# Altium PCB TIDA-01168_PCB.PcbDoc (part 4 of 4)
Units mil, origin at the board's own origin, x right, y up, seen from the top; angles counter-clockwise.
Board outline 7874.02 x 8344.02 mil, 4 copper layers (Top Layer, Signal Layer 1, Signal Layer 2, Bottom Layer), stack 65.748 mil thick; 480 components, 223 nets, 1266 pads, 1791 vias.
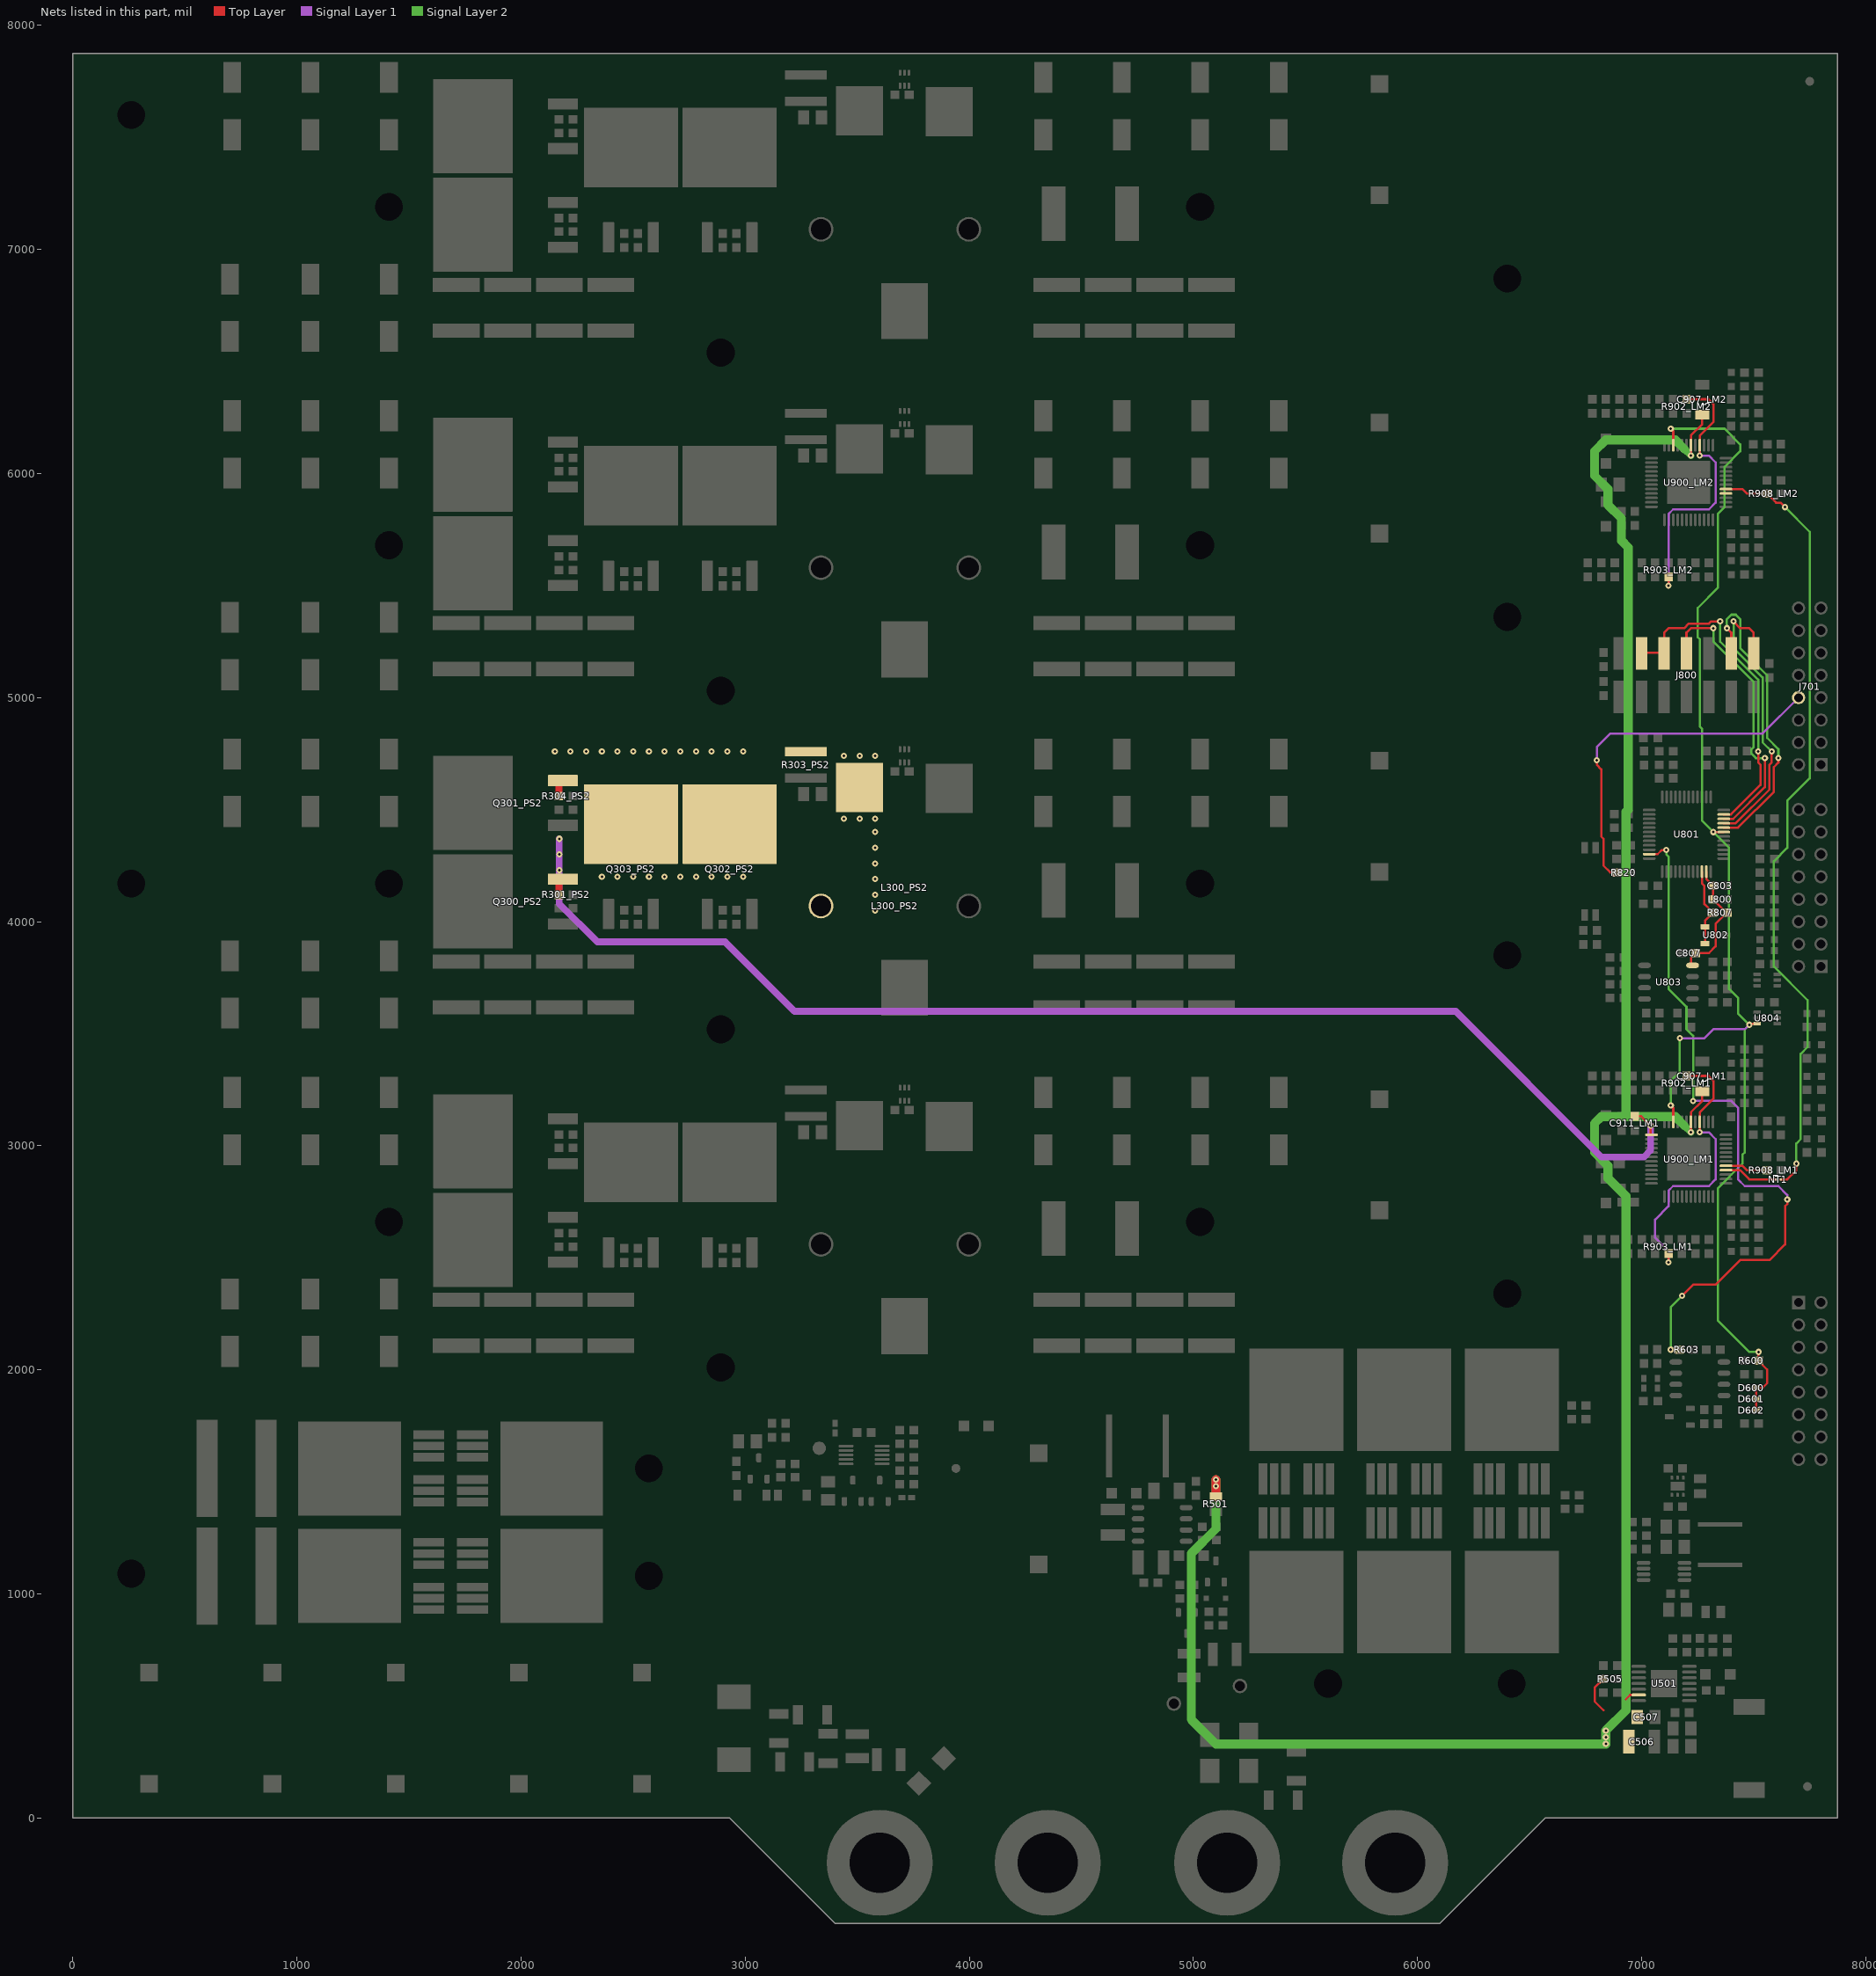
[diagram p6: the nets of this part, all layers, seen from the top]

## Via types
v1: diameter 28, hole 12, Top Layer to Bottom Layer, 1729 vias
v2: diameter 19.68, hole 7.87, Top Layer to Bottom Layer, 52 vias
v3: diameter 15.75, hole 7.87, Top Layer to Bottom Layer, 9 vias
v4: diameter 29, hole 12, Top Layer to Bottom Layer, 1 vias

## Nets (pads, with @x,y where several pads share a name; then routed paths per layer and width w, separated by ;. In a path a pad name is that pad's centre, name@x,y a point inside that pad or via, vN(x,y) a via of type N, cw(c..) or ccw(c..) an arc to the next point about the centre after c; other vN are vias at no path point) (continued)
SW2_B: C911_LM1.1 L300_PS2.2 Q300_PS2.3 Q301_PS2.3 Q302_PS2.4 Q303_PS2.4 R301_PS2.2 R303_PS2.2 R304_PS2.2 U900_LM1.13 | length 6010.6
  Top Layer w10: C911_LM1.1@6970,3131.5 6998.5,3131.5 v1(7040,3090) 7040,3051.93 U900_LM1.13@7043.66,3048.27
  Top Layer w30: R301_PS2.2@2168.5,4120 Q300_PS2.3@2168.5,4172.44 ; R304_PS2.2@2168.5,4560 2168.5,4612.44 Q301_PS2.3@2186.06,4630
  Signal Layer 1 w30: v1(2170,4370) v1(2170,4300) v1(2170,4230) 2170,4080 2340,3910 2910,3910 3220,3600 6170,3600 6820,2950 7010,2950 7040,2980 v1(7040,3090)
  other v1: 3580,4050 3580,4120 3580,4190 2360,4200 2430,4200 2500,4200 2570,4200 2640,4200 2710,4200 2780,4200 2850,4200 2920,4200 2990,4200 3580,4260 3580,4330 3580,4400 3440,4460 3510,4460 3580,4460 3440,4740 3510,4740 3580,4740 2150,4760 2220,4760 2290,4760 2360,4760 2430,4760 2500,4760 2570,4760 2640,4760 2710,4760 2780,4760 2850,4760 2920,4760 2990,4760
SYNCIN_A: U900_LM2.40
SYNCIN_B: NT1.2 U900_LM1.40 | length 240.6
  Top Layer w10: U900_LM1.40@7376.34,2890.79 7439.21,2890.79 7480,2850 NT1.2@7600,2850
SYNCOUT_A: NT1.1 R908_LM2.2 U900_LM2.41 | length 3538.2
  Top Layer w10: U900_LM2.41@7376.34,5930.47 7449.53,5930.47 7470,5910 R908_LM2.2@7558.5,5910 7560,5910 7600,5870 7620,5870 v1(7640,5850) ; NT1.1@7620,2850 7650,2850 7690,2890 v1(7690,2920)
  Signal Layer 2 w10: v1(7640,5850) 7750,5740 7750,4640 7650,4540 7650,4330 7590,4270 7590,3800 7740,3650 7740,3440 7710,3410 7710,3030 7690,3010 v1(7690,2920)
SYNCOUT_B: R908_LM1.2 U900_LM1.41 | length 190.6
  Top Layer w10: U900_LM1.41@7376.34,2910.47 7449.53,2910.47 7470,2890 R908_LM1.2@7558.5,2890
TCK: J800.9 J800.11 U801.23 | length 1484.3
  Top Layer w10: J800.11@7000,5202.31 7002.31,5200 7100,5200 7100,5290 7120,5310 7190,5310 7210,5330 7300,5330 7310,5340 v1(7350,5340) ; U801.23@7366.34,4478.58 7398.58,4478.58 7530,4610 7530,4700 7520,4710 v1(7520,4760)
  Signal Layer 2 w10: v1(7350,5340) 7350,5250 7520,5080 v1(7520,4760)
TDI: J800.3 U801.20 | length 1371.4
  Top Layer w10: U801.20@7366.34,4419.53 7429.53,4419.53 7590,4580 7590,4690 7610,4710 v1(7610,4730) ; v1(7380,5310) 7400,5290 J800.3@7400,5202.31
  Signal Layer 2 w10: v1(7380,5310) 7380,5350 7400,5370 7420,5370 7440,5350 7440,5220 7560,5100 7560,4820 7610,4770 v1(7610,4730)
TDO: J800.7 U801.22 | length 1295.1
  Top Layer w10: J800.7@7200,5202.31 7200,5290 7220,5310 v1(7320,5310) ; U801.22@7366.34,4458.9 7408.9,4458.9 7550,4600 v1(7550,4730)
  Signal Layer 2 w10: v1(7320,5310) 7320,5250 7500,5070 7500,4780 7490,4770 7490,4750 7510,4730 v1(7550,4730)
TMS: J800.1 U801.21 | length 1289.1
  Top Layer w10: U801.21@7366.34,4439.21 7419.21,4439.21 7570,4590 7570,4700 7580,4710 v1(7580,4760) ; v1(7410,5340) 7440,5310 7480,5310 7500,5290 J800.1@7500,5202.31
  Signal Layer 2 w10: v1(7410,5340) 7410,5220 7540,5090 7540,4800 v1(7580,4760)
TXD: J701.8 R820.1 | length 1604.5
  Top Layer w10: v1(6800,4720) 6800,4700 6820,4680 6820,4380 6830,4370 6830,4250 6860,4220 R820.1@6888.5,4220
  Signal Layer 1 w10: v1(6800,4720) 6800,4780 6860,4840 7540,4840 J701.8@7700,5000
UVLO: D600.2 D601.2 D602.2 R600.1 U801.19 U804.3 U900_LM1.10 U900_LM2.10 | length 5923.3
  Top Layer w10: v1(7130,3180) 7141.1,3168.9 U900_LM1.10@7141.1,3106.34 ; v1(7130,6200) 7141.1,6188.9 U900_LM2.10@7141.1,6126.34 ; v1@7320,4400 v1(7320,4399.84) U801.19@7366.34,4399.84 ; v1(7480,3540) 7484.41,3544.41 U804.3@7515.71,3544.41 ; D602.2@7511.65,1820 D601.2@7511.65,1870 D600.2@7511.65,1920 7540,1920 7560,1940 7560,2001.5 R600.1@7521.5,2040 v1(7521.5,2080)
  Signal Layer 1 w10: v1(7170,3480) 7280,3480 7320,3520 7460,3520 v1(7480,3540)
  Signal Layer 2 w10: v1(7130,3180) 7130,3290 7170,3330 v1(7170,3480) ; v1(7130,6200) 7370,6200 7440,6130 7440,6100 7370,6030 7370,5850 7340,5820 7340,5490 7250,5400 7250,5270 7260,5260 7260,4870 7270,4860 7270,4450 v1@7320,4400 ; v1(7320,4399.84) 7390,4329.84 7390,3700 7430,3660 7430,3590 v1(7480,3540) 7460,3520 7460,2970 7450,2960 7450,2920 7340,2810 7340,2220 7480,2080 v1@7520,2080
VDDA: C803.2 C807.1 L800.2 R807.1 U801.11 U803.8 | length 545.6
  Top Layer w10: U803.8@7226.54,3804.25 7220,3810.79 7220,3838.5 C807.1@7231.81,3850.31 ; C807.1@7241.5,3860 7300,3860 7330,3890 7330,3990 7378.5,4038.5 7378.5,4040 L800.2@7318.5,4100 C803.2@7318.5,4160 7288.58,4189.92 U801.11@7288.58,4223.66
VIN_LM: C506.1 C507.1 C907_LM1.1 C907_LM2.1 R501.2 R505.1 U501.13 U900_LM1.6 U900_LM2.6 | length 10583.7
  Top Layer w10: R505.1@6828.5,620 6790,581.5 6790,520 6830,480 ; 6930,530 6948.82,548.82 U501.13@6986.81,548.82 ; U900_LM1.6@7219.69,3106.18 7219.69,3149.69 7269.84,3199.84 C907_LM1.1@7269.84,3242.91 ; v1(7219.84,3060) U900_LM1.6@7219.84,3106.34 ; v1(7219.84,6080) U900_LM2.6@7219.84,6126.34 7219.84,6169.84 7270,6220 C907_LM2.1@7270,6263.07
  Top Layer w40: R501.2@5100,1434.65 v1(5100,1510)
  Signal Layer 2 w30: 7190,3089.84 v1(7219.84,3060) ; 7190,6109.84 v1(7219.84,6080)
  Signal Layer 2 w40: v1(5100,1510) 5100,1290 4990,1180 4990,440 5100,330 v1(6840,330) v1(6840,390) 6930,480 6930,2775.11 6850,2855.11 6850,2910 6790,2970 6790,3100 6820,3130 7149.84,3130 7190,3089.84 ; 6930,3130 6930,4490 6940,4500 6940,5670 6910,5700 6910,5800 6850,5860 6850,5930 6790,5990 6790,6100 6840,6150 7149.84,6150 7190,6109.84
  other v1: 6840,360 5100,1480
VINX_LM1: R902_LM1.2 R903_LM1.2 U900_LM1.4 | length 1286.2
  Top Layer w10: v1(7120,2480) R903_LM1.2@7120,2518.5 ; R902_LM1.2@7200,3311.5 7298.5,3311.5 7320,3290 7320,3210 7259.21,3149.21 U900_LM1.4@7259.21,3106.34 v1(7259.21,3060)
  Signal Layer 1 w10: v1(7120,2480) 7120,2530 7060,2590 7060,2670 7120,2730 7120,2800 7140,2820 7300,2820 7330,2850 7330,3030 7300,3060 v1(7259.21,3060)
VINX_LM2: R902_LM2.2 R903_LM2.2 U900_LM2.4 | length 1237.3
  Top Layer w10: v1(7120,5500) R903_LM2.2@7120,5538.5 ; R902_LM2.2@7200,6331.5 7298.5,6331.5 7320,6310 7320,6230 7259.21,6169.21 U900_LM2.4@7259.21,6126.34 v1(7259.21,6080) v1@7260,6080
  Signal Layer 1 w10: v1(7120,5500) 7120,5820 7140,5840 7300,5840 7330,5870 7330,6050 7300,6080 v1(7259.21,6080)
VREF: R807.2 U801.10 U802.1 U802.2 | length 356.4
  Top Layer w10: U801.10@7268.9,4223.66 7268.9,4171.1 7280,4160 7280,4078.5 R807.2@7318.5,4040 7282.76,4004.25 U802.1@7282.76,3977.4 U802.2@7282.76,3902.6
WDT_TRIG: R603.1 U801.47 | length 3113.4
  Top Layer w10: U801.47@7033.66,4301.42 7071.42,4301.42 7090,4320 v1(7110,4320) ; v1(7130,2090) R603.1@7168.5,2090 ; v1(7180,2330) 7230,2380 7330,2380 7440,2490 7570,2490 7640,2560 7640,2730 7649.56,2739.56 v4(7649.56,2760)
  Signal Layer 1 w10: v1(7230,3200) 7400,3200 7430,3170 7430,2850 7460,2820 7610,2820 7649.56,2780.44 v4(7649.56,2760)
  Signal Layer 2 w10: v1(7110,4320) 7110,4300 7120,4290 7120,3700 7200,3620 7200,3520 7230,3490 v1(7230,3200) ; v1(7130,2090) 7130,2280 v1(7180,2330)
pads on no net: D101.2 D105.2 FID1.1 FID2.1 FID3.1 J800.6 L300_PS1.3 L300_PS2.3 L300_PS3.3 L300_PS4.3 MH1.1 MH2.1 MH3.1 MH4.1 MH6.1 MH7.1 MH8.1 MH9.1 MH10.1 MH11.1 MH12.1 MH13.1 MH14.1 MH16.1 MH17.1 MH18.1 MH19.1 MH20.1 MH21.1 MH25.1 MH26.1 MH27.1 MH28.1 U502.1 U502.4 U502.5 U503.2 U503.3 U503.7@7142.28,1480 U503.7@7177.72,1480 U801.30 U801.46 U900_LM1.3 U900_LM1.5 U900_LM1.7 U900_LM1.16 U900_LM1.21 U900_LM1.32 U900_LM2.3 U900_LM2.5 U900_LM2.7 U900_LM2.16 U900_LM2.21 U900_LM2.32

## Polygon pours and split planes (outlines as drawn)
BRKS on Top Layer "TOP_LAYER_BRKS_P740" (solid, pour order 740): 6650,1600 6650,1230 5220,1230 5220,1600
NetD102_2 on Top Layer "TOP_LAYER_NETD102_2_P736" (solid, pour order 736): 1500,1800 1870,1800 1870,840 1500,840
CS1B_A on Top Layer "TOP_LAYER_CS1B_A_P692" (solid, pour order 692): 4150,3100 4150,2960 4330,2780 4640,2780 4640,2480 4150,2480 4150,2350 4280,2220 5220,2220 5220,1620 6150,1620 6150,2950 5700,2950 5550,3100
GND on Top Layer "TOP_LAYER_GND_P688" (solid, remove dead copper, pour order 688): 4150,3310 4150,3120 5560,3120 5710,2970 6130,2970 6130,3310
CS1A_B on Top Layer "TOP_LAYER_CS1A_B_P684" (solid, remove dead copper, pour order 684): 3800,3310 4130,3310 4130,2950 4320,2760 4440,2760 4440,2500 4320,2500 3800,2500
SW1_B on Top Layer "TOP_LAYER_SW1_B_P680" (solid, pour order 680): 2110,2650 3080,2650 3230,2500 3620,2500 3620,3310 2110,3310
P48V_NF on Top Layer "TOP_LAYER_P48V_NF_P643" (solid, pour order 643): 510,2220 2540,2220 2540,2430 2090,2430 2090,3310 1590,3310 1590,3100 510,3100
GND on Top Layer "TOP_LAYER_GND_P676" (solid, remove dead copper, pour order 676): 530,3310 530,3120 1570,3120 1570,3310
GND on Top Layer "TOP_LAYER_GND_P672" (solid, pour order 672): 530,2200 2560,2200 2560,2630 3070,2630 3220,2480 4130,2480 4130,2340 4270,2200 5200,2200 5200,1820 530,1820
CS1B_A on Top Layer "TOP_LAYER_CS1B_A_P693" (solid, pour order 693): 4150,4610 4150,4470 4330,4290 4640,4290 4640,3990 4150,3990 4150,3860 4280,3730 5220,3730 5220,3330 6150,3330 6150,4460 5700,4460 5550,4610
GND on Top Layer "TOP_LAYER_GND_P689" (solid, remove dead copper, pour order 689): 4150,4820 4150,4630 5560,4630 5710,4480 6130,4480 6130,4820
CS2A_B on Top Layer "TOP_LAYER_CS2A_B_P685" (solid, remove dead copper, pour order 685): 3800,4820 4130,4820 4130,4460 4320,4270 4440,4270 4440,4010 4320,4010 3800,4010
SW2_B on Top Layer "TOP_LAYER_SW2_B_P681" (solid, pour order 681): 2110,4160 3080,4160 3230,4010 3620,4010 3620,4820 2110,4820
P48V_NF on Top Layer "TOP_LAYER_P48V_NF_P644" (solid, pour order 644): 510,3730 2540,3730 2540,3940 2090,3940 2090,4820 1590,4820 1590,4610 510,4610
GND on Top Layer "TOP_LAYER_GND_P677" (solid, remove dead copper, pour order 677): 530,4820 530,4630 1570,4630 1570,4820
GND on Top Layer "TOP_LAYER_GND_P673" (solid, pour order 673): 530,3710 2560,3710 2560,4140 3070,4140 3220,3990 4130,3990 4130,3850 4270,3710 5200,3710 5200,3330 530,3330
CS1B_A on Top Layer "TOP_LAYER_CS1B_A_P694" (solid, pour order 694): 4150,6120 4150,5980 4330,5800 4640,5800 4640,5500 4150,5500 4150,5370 4280,5240 5220,5240 5220,4840 6150,4840 6150,5970 5700,5970 5550,6120
GND on Top Layer "TOP_LAYER_GND_P690" (solid, remove dead copper, pour order 690): 4150,6330 4150,6140 5560,6140 5710,5990 6130,5990 6130,6330
CS1A_A on Top Layer "TOP_LAYER_CS1A_A_P686" (solid, remove dead copper, pour order 686): 3800,6330 4130,6330 4130,5970 4320,5780 4440,5780 4440,5520 4320,5520 3800,5520
SW1_A on Top Layer "TOP_LAYER_SW1_A_P682" (solid, pour order 682): 2110,5670 3080,5670 3230,5520 3620,5520 3620,6330 2110,6330
P48V_NF on Top Layer "TOP_LAYER_P48V_NF_P645" (solid, pour order 645): 510,5240 2540,5240 2540,5450 2090,5450 2090,6330 1590,6330 1590,6120 510,6120
GND on Top Layer "TOP_LAYER_GND_P678" (solid, remove dead copper, pour order 678): 530,6330 530,6140 1570,6140 1570,6330
GND on Top Layer "TOP_LAYER_GND_P674" (solid, pour order 674): 530,5220 2560,5220 2560,5650 3070,5650 3220,5500 4130,5500 4130,5360 4270,5220 5200,5220 5200,4840 530,4840
GND on Top Layer "TOP_LAYER_GND_P675" (solid, pour order 675): 530,6730 2560,6730 2560,7160 3070,7160 3220,7010 4130,7010 4130,6870 4270,6730 5200,6730 5200,6350 530,6350
GND on Top Layer "TOP_LAYER_GND_P679" (solid, remove dead copper, pour order 679): 530,7840 530,7650 1570,7650 1570,7840
P48V_NF on Top Layer "TOP_LAYER_P48V_NF_P646" (solid, pour order 646): 510,6750 2540,6750 2540,6960 2090,6960 2090,7840 1590,7840 1590,7630 510,7630
SW2_A on Top Layer "TOP_LAYER_SW2_A_P683" (solid, pour order 683): 2110,7180 3080,7180 3230,7030 3620,7030 3620,7840 2110,7840
CS2A_A on Top Layer "TOP_LAYER_CS2A_A_P687" (solid, remove dead copper, pour order 687): 3800,7840 4130,7840 4130,7480 4320,7290 4440,7290 4440,7030 4320,7030 3800,7030
GND on Top Layer "TOP_LAYER_GND_P691" (solid, remove dead copper, pour order 691): 4150,7840 4150,7650 5560,7650 5710,7500 6130,7500 6130,7840
CS1B_A on Top Layer "TOP_LAYER_CS1B_A_P695" (solid, pour order 695): 4150,7630 4150,7490 4330,7310 4640,7310 4640,7010 4150,7010 4150,6880 4280,6750 5220,6750 5220,6350 6150,6350 6150,7480 5700,7480 5550,7630
P48V_NF on Top Layer "TOP_LAYER_P48V_NF_P752" (solid, remove dead copper, pour order 752): 10,840 670,840 670,1800 510,1800 510,7840 10,7840 10,840
CS1B_A on Top Layer "TOP_LAYER_CS1B_A_P754" (solid, remove dead copper, pour order 754): 6150,1620 6650,1620 6650,7840 6150,7840
KL30 on Top Layer "TOP_LAYER_KL30_P756" (solid, remove dead copper, pour order 756): 5220,1210 5220,1180 5110,1070 5110,940 5170,880 5170,310 5300,310 5360,250 5530,250 5530,-460 6090,-460 6570,20 6570,330 6650,410 6650,1210
KL40 on Top Layer "TOP_LAYER_KL40_P758" (solid, pour order 758): 1890,1800 2900,1800 2900,1370 4020,1370 4020,1000 4250,1000 4720,530 4720,-460 3980,-460 3980,80 3720,340 3310,340 3310,550 3100,550 2810,840 1890,840
BRKS on Bottom Layer "BOTTOM_LAYER_BRKS_P744" (solid, remove dead copper, pour order 744): 5220,1600 6650,1600 6650,1230 5220,1230
NetD102_2 on Bottom Layer "BOTTOM_LAYER_NETD102_2_P738" (solid, pour order 738): 1500,1800 1870,1800 1870,840 1500,840
SW1_B on Bottom Layer "BOTTOM_LAYER_SW1_B_P696" (solid, pour order 696): 2110,2650 3080,2650 3230,2500 3620,2500 3620,3310 2110,3310
CS1A_B on Bottom Layer "BOTTOM_LAYER_CS1A_B_P708" (solid, remove dead copper, pour order 708): 3800,3310 4130,3310 4130,2950 4320,2760 4440,2760 4440,2500 4320,2500 3800,2500
GND on Bottom Layer "BOTTOM_LAYER_GND_P712" (solid, pour order 712): 510,3310 2090,3310 2090,2430 2560,2430 2560,2630 3070,2630 3220,2480 4130,2480 4640,2480 4640,2780 4330,2780 4150,2960 4150,3120 4150,3310 6150,3310 6150,1820 510,1820
SW2_B on Bottom Layer "BOTTOM_LAYER_SW2_B_P697" (solid, pour order 697): 2110,4160 3080,4160 3230,4010 3620,4010 3620,4820 2110,4820
CS2A_B on Bottom Layer "BOTTOM_LAYER_CS2A_B_P709" (solid, remove dead copper, pour order 709): 3800,4820 4130,4820 4130,4460 4320,4270 4440,4270 4440,4010 4320,4010 3800,4010
GND on Bottom Layer "BOTTOM_LAYER_GND_P713" (solid, pour order 713): 510,4820 2090,4820 2090,3940 2560,3940 2560,4140 3070,4140 3220,3990 4130,3990 4640,3990 4640,4290 4330,4290 4150,4470 4150,4630 4150,4820 6150,4820 6150,3330 510,3330
SW1_A on Bottom Layer "BOTTOM_LAYER_SW1_A_P698" (solid, pour order 698): 2110,5670 3080,5670 3230,5520 3620,5520 3620,6330 2110,6330
CS1A_A on Bottom Layer "BOTTOM_LAYER_CS1A_A_P710" (solid, remove dead copper, pour order 710): 3800,6330 4130,6330 4130,5970 4320,5780 4440,5780 4440,5520 4320,5520 3800,5520
GND on Bottom Layer "BOTTOM_LAYER_GND_P714" (solid, pour order 714): 510,6330 2090,6330 2090,5450 2560,5450 2560,5650 3070,5650 3220,5500 4130,5500 4640,5500 4640,5800 4330,5800 4150,5980 4150,6140 4150,6330 6150,6330 6150,4840 510,4840
GND on Bottom Layer "BOTTOM_LAYER_GND_P715" (solid, pour order 715): 510,7840 2090,7840 2090,6960 2560,6960 2560,7160 3070,7160 3220,7010 4130,7010 4640,7010 4640,7310 4330,7310 4150,7490 4150,7650 4150,7840 6150,7840 6150,6350 510,6350
CS2A_A on Bottom Layer "BOTTOM_LAYER_CS2A_A_P711" (solid, remove dead copper, pour order 711): 3800,7840 4130,7840 4130,7480 4320,7290 4440,7290 4440,7030 4320,7030 3800,7030
SW2_A on Bottom Layer "BOTTOM_LAYER_SW2_A_P699" (solid, pour order 699): 2110,7180 3080,7180 3230,7030 3620,7030 3620,7840 2110,7840
GND on Bottom Layer "BOTTOM_LAYER_GND_P748" (solid, pour order 748): 4040,1820 5200,1820 5200,1190 5150,1140 5150,950 5150,390 6670,390 6670,7840 7850,7840 7850,20 6580,20 6500,100 5600,100 5510,10 5510,-470 4740,-470 4740,540 4260,1020 4040,1020
GND on Bottom Layer "BOTTOM_LAYER_GND_P750" (solid, remove dead copper, pour order 750): 2830,1800 4020,1800 4020,1020 3960,960 3960,340 3310,340 2830,820 2830,830
GND on Bottom Layer "BOTTOM_LAYER_GND_P760" (solid, remove dead copper, pour order 760): 10,7840 510,7840 510,10 10,10
GND on Bottom Layer "BOTTOM_LAYER_GND_P762" (solid, remove dead copper, pour order 762): 6150,1820 6650,1820 6650,7840 6150,7840
KL40 on Bottom Layer "BOTTOM_LAYER_KL40_P764" (solid, remove dead copper, pour order 764): 1890,840 2810,840 2810,1800 1890,1800
KL30 on Bottom Layer "BOTTOM_LAYER_KL30_P768" (solid, remove dead copper, pour order 768): 5220,1210 6650,1210 6650,410 5170,410 5170,1130 5220,1180
GND on Bottom Layer "BOTTOM_LAYER_GND_P772" (solid, remove dead copper, pour order 772): 510,820 2830,820 3310,340 3960,340 3960,-460 3410,-460 2940,10 510,10
BRKS on Signal Layer 2 "SIGNAL_LAYER_2_BRKS_P742" (solid, remove dead copper, pour order 742): 5220,1600 6650,1600 6650,1230 5220,1230
NetD102_2 on Signal Layer 2 "SIGNAL_LAYER_2_NETD102_2_P737" (solid, pour order 737): 1500,1800 1870,1800 1870,840 1500,840
SW1_B on Signal Layer 2 "SIGNAL_LAYER_2_SW1_B_P700" (solid, pour order 700): 2110,2650 3080,2650 3230,2500 3620,2500 3620,3310 2110,3310
CS1A_B on Signal Layer 2 "SIGNAL_LAYER_2_CS1A_B_P704" (solid, remove dead copper, pour order 704): 3800,3310 4130,3310 4130,2950 4320,2760 4440,2760 4440,2500 4320,2500 3800,2500
P48V_NF on Signal Layer 2 "SIGNAL_LAYER_2_P48V_NF_P716" (solid, remove dead copper, pour order 716): 510,3100 1590,3100 1590,3310 2090,3310 2090,2430 2540,2430 2540,2220 510,2220
GND on Signal Layer 2 "SIGNAL_LAYER_2_GND_P724" (solid, remove dead copper, pour order 724): 4150,3310 6130,3310 6130,2970 5710,2970 5560,3120 4150,3120
GND on Signal Layer 2 "SIGNAL_LAYER_2_GND_P720" (solid, remove dead copper, pour order 720): 530,3310 1570,3310 1570,3120 530,3120
GND on Signal Layer 2 "SIGNAL_LAYER_2_GND_P728" (solid, pour order 728): 530,2200 2560,2200 2560,2630 3070,2630 3220,2480 4130,2480 4130,2340 4270,2200 5200,2200 5200,1820 530,1820
CS1B_A on Signal Layer 2 "SIGNAL_LAYER_2_CS1B_A_P732" (solid, pour order 732): 4150,3100 4150,2960 4330,2780 4640,2780 4640,2480 4150,2480 4150,2350 4280,2220 5220,2220 5220,1820 6150,1820 6150,2950 5700,2950 5550,3100
SW2_B on Signal Layer 2 "SIGNAL_LAYER_2_SW2_B_P701" (solid, pour order 701): 2110,4160 3080,4160 3230,4010 3620,4010 3620,4820 2110,4820
CS2A_B on Signal Layer 2 "SIGNAL_LAYER_2_CS2A_B_P705" (solid, remove dead copper, pour order 705): 3800,4820 4130,4820 4130,4460 4320,4270 4440,4270 4440,4010 4320,4010 3800,4010
P48V_NF on Signal Layer 2 "SIGNAL_LAYER_2_P48V_NF_P717" (solid, remove dead copper, pour order 717): 510,4610 1590,4610 1590,4820 2090,4820 2090,3940 2540,3940 2540,3730 510,3730
GND on Signal Layer 2 "SIGNAL_LAYER_2_GND_P725" (solid, remove dead copper, pour order 725): 4150,4820 6130,4820 6130,4480 5710,4480 5560,4630 4150,4630
GND on Signal Layer 2 "SIGNAL_LAYER_2_GND_P721" (solid, remove dead copper, pour order 721): 530,4820 1570,4820 1570,4630 530,4630
GND on Signal Layer 2 "SIGNAL_LAYER_2_GND_P729" (solid, pour order 729): 530,3710 2560,3710 2560,4140 3070,4140 3220,3990 4130,3990 4130,3850 4270,3710 5200,3710 5200,3330 530,3330
CS1B_A on Signal Layer 2 "SIGNAL_LAYER_2_CS1B_A_P733" (solid, pour order 733): 4150,4610 4150,4470 4330,4290 4640,4290 4640,3990 4150,3990 4150,3860 4280,3730 5220,3730 5220,3330 6150,3330 6150,4460 5700,4460 5550,4610
SW1_A on Signal Layer 2 "SIGNAL_LAYER_2_SW1_A_P702" (solid, pour order 702): 2110,5670 3080,5670 3230,5520 3620,5520 3620,6330 2110,6330
CS1A_A on Signal Layer 2 "SIGNAL_LAYER_2_CS1A_A_P706" (solid, remove dead copper, pour order 706): 3800,6330 4130,6330 4130,5970 4320,5780 4440,5780 4440,5520 4320,5520 3800,5520
P48V_NF on Signal Layer 2 "SIGNAL_LAYER_2_P48V_NF_P718" (solid, remove dead copper, pour order 718): 510,6120 1590,6120 1590,6330 2090,6330 2090,5450 2540,5450 2540,5240 510,5240
GND on Signal Layer 2 "SIGNAL_LAYER_2_GND_P726" (solid, remove dead copper, pour order 726): 4150,6330 6130,6330 6130,5990 5710,5990 5560,6140 4150,6140
GND on Signal Layer 2 "SIGNAL_LAYER_2_GND_P722" (solid, remove dead copper, pour order 722): 530,6330 1570,6330 1570,6140 530,6140
GND on Signal Layer 2 "SIGNAL_LAYER_2_GND_P730" (solid, pour order 730): 530,5220 2560,5220 2560,5650 3070,5650 3220,5500 4130,5500 4130,5360 4270,5220 5200,5220 5200,4840 530,4840
CS1B_A on Signal Layer 2 "SIGNAL_LAYER_2_CS1B_A_P734" (solid, pour order 734): 4150,6120 4150,5980 4330,5800 4640,5800 4640,5500 4150,5500 4150,5370 4280,5240 5220,5240 5220,4840 6150,4840 6150,5970 5700,5970 5550,6120
CS1B_A on Signal Layer 2 "SIGNAL_LAYER_2_CS1B_A_P735" (solid, pour order 735): 4150,7630 4150,7490 4330,7310 4640,7310 4640,7010 4150,7010 4150,6880 4280,6750 5220,6750 5220,6350 6150,6350 6150,7480 5700,7480 5550,7630
GND on Signal Layer 2 "SIGNAL_LAYER_2_GND_P731" (solid, pour order 731): 530,6730 2560,6730 2560,7160 3070,7160 3220,7010 4130,7010 4130,6870 4270,6730 5200,6730 5200,6350 530,6350
GND on Signal Layer 2 "SIGNAL_LAYER_2_GND_P723" (solid, remove dead copper, pour order 723): 530,7840 1570,7840 1570,7650 530,7650
GND on Signal Layer 2 "SIGNAL_LAYER_2_GND_P727" (solid, remove dead copper, pour order 727): 4150,7840 6130,7840 6130,7500 5710,7500 5560,7650 4150,7650
P48V_NF on Signal Layer 2 "SIGNAL_LAYER_2_P48V_NF_P719" (solid, remove dead copper, pour order 719): 510,7630 1590,7630 1590,7840 2090,7840 2090,6960 2540,6960 2540,6750 510,6750
CS2A_A on Signal Layer 2 "SIGNAL_LAYER_2_CS2A_A_P707" (solid, remove dead copper, pour order 707): 3800,7840 4130,7840 4130,7480 4320,7290 4440,7290 4440,7030 4320,7030 3800,7030
SW2_A on Signal Layer 2 "SIGNAL_LAYER_2_SW2_A_P703" (solid, pour order 703): 2110,7180 3080,7180 3230,7030 3620,7030 3620,7840 2110,7840
KL40 on Signal Layer 2 "SIGNAL_LAYER_2_KL40_P766" (solid, remove dead copper, pour order 766): 1890,1800 2810,1800 2810,840 1890,840
KL30 on Signal Layer 2 "SIGNAL_LAYER_2_KL30_P770" (solid, remove dead copper, pour order 770): 5220,1210 6650,1210 6650,410 5170,410 5170,1130 5220,1180

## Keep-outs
Keep-Out Layer:
  text ".Layer_Name" at 577,-858.49 h60

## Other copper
Top Layer:
  region net P3V3: 7160,1580 7290,1580 7290,1490 7220,1490 7220,1510 7180,1510 7180,1540 7160,1540
  region net NetC514_1: 7160,1350 7290,1350 7290,1470 7220,1470 7220,1450 7180,1450 7180,1420 7160,1420
  region net GND: 7140,1580 7140,1540 7120,1540 7120,1500 7210,1500 7210,1460 7120,1460 7120,1410 7150,1410 7150,1350 7050,1350 7050,1580
  region net NetC501_1: 5070,1390 5170,1390 5170,1270 5070,1270
  region net NetC514_1: 7160,1350 7450,1350 7450,1300 7300,1300 7251,1251 7230,1251 7230,1170 7160,1170
  region net P10V: 7170,1040 7230.2,1040 7240.2,1050 7240.2,1069.8 7230,1080 7230,1090 7310.2,1090 7310.2,880 7170,880
  region net GND: 7050,1350 7150,1350 7150,880 7050,880
  region net VIN_LM: 6820,270 7010,270 7010,490 6950,490 6940,500 6940,540 6930,540 6920,530 6870,530 6870,500 6860,490 6820,490
  region net NetC505_2: 7280,540 7330,540 7330,690 7560,690 7560,450 7340,450 7280,510
  region net NetC508_1: 7190,490 7270,490 7320,440 7320,320 7380,260 7470,260 7560,170 7560,80 7380,80 7190,270
  region net GND: 7040,760 7160,760 7160,500 7170,490 7170,270 7030,270 7030,490 7040,500
  region net GND: 4259.79,1020 4880,1020 4900,1000 4920,1000 4930,990 4930,870 4900,840 4900,650 5150,650 5150,540 4739.79,540
  region net KL30_POL: 5000,1080 5090,1080 5130,1120 5130,1200 5000,1200
  region net KL30_BIAS: 4840,1080 4980,1080 4980,1200 4940,1200 4920,1220.5 4920,1250 4950,1280 4950,1290 4920,1320 4920,1400 4940,1420 4970,1420 4970,1500 4900,1500 4880,1480 4880,1410 4840,1370
  region net NetL500_1: 4791.34,1556.75 4790,1556.75 4790,1420 4860,1420 4860,1490.47 4889.76,1520.24 4889.76,1556.75
  region net NetD501_2: 4720,1500 4720,1508.9 4708.66,1520.24 4708.66,1556.75 4733.25,1556.75 4770,1520 4770,1500
  region net NetD501_2: 4720,1370 4720,1500 4770,1500 4770,1410 4790,1390 4790,1370
  region net NetC501_1: 4040,1800 4590,1800 4590,1500 4700,1500 4700,1340 4580,1340 4530,1390 4040,1390
  region net GND: 4040,1370 4520,1370 4580,1310 4710,1310 4710,1270 4730,1250 4800,1250 4800,1020 4040,1020
  region net GND: 5510,-450 5510,10 5390,10 5390,230 5350,230 5300,280 5170,280 5170,130 5000,130 5000,450 5150,450 5150,540 4740,540 4740,-450
  region net NetD402_2: 5020,430 5150,430 5150,150 5020,150
  region net NetC401_2: 5150,670 5150,790 4920,790 4920,670
  region net NetC400_2: 5410,30 5410,230 5510,230 5510,30
  region net NetC100_2: 3440,320 3440,200 3630,200 3630,320
  region net NetC102_2: 3230,200 3230,320 3420,320 3420,200
  region net NetC101_2: 3100,410 3290,410 3290,530 3100,530
  region net P48V: 690,1800 1480,1800 1480,820 2800,820 3080,540 3080,410 20,410 20,820 690,820
  pour cut-out: 3160,3160 3380,3160 3380,3010 3160,3010
  pour cut-out: 2110,2879.54 2270,2879.54 2270,3090 2110,3090
  region net GND: 3290,3100 3180,3100 3180,3020 3290,3020
  pour cut-out: 2789.54,2610 2789.54,2440 3000,2440 3000,2610
  pour cut-out: 3160,4670 3380,4670 3380,4520 3160,4520
  pour cut-out: 2110,4389.54 2270,4389.54 2270,4600 2110,4600
  region net GND: 3290,4610 3180,4610 3180,4530 3290,4530
  pour cut-out: 2789.54,4120 2789.54,3950 3000,3950 3000,4120
  pour cut-out: 3160,6180 3380,6180 3380,6030 3160,6030
  pour cut-out: 2110,5899.54 2270,5899.54 2270,6110 2110,6110
  region net GND: 3290,6120 3180,6120 3180,6040 3290,6040
  pour cut-out: 2789.54,5630 2789.54,5460 3000,5460 3000,5630
  region net GND: 3290,7630 3180,7630 3180,7550 3290,7550
  pour cut-out: 3160,7690 3380,7690 3380,7540 3160,7540
  pour cut-out: 2789.54,7140 2789.54,6970 3000,6970 3000,7140
  pour cut-out: 2110,7409.54 2270,7409.54 2270,7620 2110,7620
  region net GND: 20,390 20,20 2940,20 3410,-450 3960,-450 3960,70 3710,320 3650,320 3650,180 3210,180 3210,390
  text ".Layer_Name" at 577,-858.49 h60
Signal Layer 1:
  region net NetC501_1: 4590,1500 4960,1500 5030,1430 5170,1430 5170,1270 4770,1270 4700,1340 4590,1340
  region net GND: 3230,3100 3230,2540 3150,2460 3060,2460 3060,3040 3120,3100
  region net GND: 3230,4610 3230,4050 3150,3970 3060,3970 3060,4550 3120,4610
  region net GND: 3230,6120 3230,5560 3150,5480 3060,5480 3060,6060 3120,6120
  region net GND: 3230,7630 3230,7070 3150,6990 3060,6990 3060,7570 3120,7630
Signal Layer 2:
  region net P48V: 1480,1800 690,1800 690,840 1480,840
  region net CS1B_A: 5220,1800 5220,1620 6650,1620 6650,1800
Bottom Layer:
  pour cut-out: 6670,1850 6700,1850 6710,1860 6710,1880 6700,1890 6670,1890
  region net P48V: 690,1800 1480,1800 1480,840 690,840
  region net CS1B_A: 5220,1800 5220,1620 6650,1620 6650,1800
  text ".Layer_Name" at 577,-858.49 h60

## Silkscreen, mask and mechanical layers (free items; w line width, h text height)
Top Overlay:
  text ".Layer_Name" at 577,-858.49 h60
Bottom Overlay:
  text ".Layer_Name" at 577,-858.49 h60
Top Paste:
  text ".Layer_Name" at 577,-858.49 h60
Bottom Paste:
  text ".Layer_Name" at 577,-858.49 h60
Top Solder:
  region: 5540,-450 6080,-450 6560,30 6560,340 6640,420 6640,720 5250,720 5250,510 5410,350 5510,350 5540,320
  region: 2380,1790 2890,1790 2890,1350 4010,1350 4010,990 4240,990 4710,520 4710,-450 3990,-450 3990,270 3890,370 3700,370 3510,560 3110,560 2820,850 2380,850
  region: 6160,2110 6640,2110 6640,7830 6160,7830
  region: 4840,2900 5370,2900 5680,2590 6160,2590 6160,2110 5230,2110 5230,2360 5220,2370 4840,2370
  region: 4840,4410 5370,4410 5680,4100 6160,4100 6160,3480 5230,3480 5230,3870 5220,3880 4840,3880
  region: 4840,5920 5370,5920 5680,5610 6160,5610 6160,4990 5230,4990 5230,5380 5220,5390 4840,5390
  region: 4840,7430 5370,7430 5680,7120 6160,7120 6160,6500 5230,6500 5230,6890 5220,6900 4840,6900
  region: 500,7830 500,7430 1580,7430 1580,6950 500,6950 500,5920 1580,5920 1580,5440 500,5440 500,4410 1580,4410 1580,3930 500,3930 500,2900 1580,2900 1580,2420 500,2420 500,850 20,850 20,7830
  text ".Layer_Name" at 577,-858.49 h60
  text ".Layer_Name" at 577,-858.49 h60
Bottom Solder:
  region: 500,6730 2500,6730 2700,6930 4100,6930 4300,6730 6160,6730 6160,6360 500,6360
  region: 500,5220 2500,5220 2700,5420 4100,5420 4300,5220 6160,5220 6160,4850 500,4850
  region: 500,3710 2500,3710 2700,3910 4100,3910 4300,3710 6160,3710 6160,3340 500,3340
  region: 500,2200 2500,2200 2700,2400 4100,2400 4300,2200 6160,2200 6160,1830 500,1830
  region: 6640,7830 6160,7830 6160,1830 6640,1830
  region: 5500,-450 5500,320 5440,380 5140,380 5140,760 4650,1250 4650,1830 4050,1830 4050,1030 4270,1030 4750,550 4750,-450
  region: 3950,-450 3950,330 3300,330 2820,810 500,810 500,7830 20,7830 20,20 2950,20 3420,-450
  text ".Layer_Name" at 577,-858.49 h60
Drill Guide:
  text ".Layer_Name" at 577,-858.49 h60
M1 Board Outline:
  the board outline again, w10
  text ".Layer_Name" at 577,-858.49 h60
M2 Board Dimensions:
  rectangle: 125,-400 500,-275
  rectangle: 0,-275 125,-150
  lines w7: 0,-275 1000,-275 ; 125,-400 125,-150 ; 250,-400 250,-150 ; 500,-400 500,-150 ; 750,-400 750,-150 ; 0,-400 0,-150 1000,-150 1000,-400 0,-400
  text ".Layer_Name" at 577,-858.49 h60
M3 3D STEP Top:
  text ".Layer_Name" at 577,-858.49 h60
M4 3D STEP Bottom:
  text ".Layer_Name" at 577,-858.49 h60
M5 Assembly Top:
  lines w10: -292,-930.17 6308,-930.17 ; -292,-726.83 6310,-726.83 ; -292,-523.5 -292,-1133.5 3713,-1133.5 6310,-1133.5 6310,-523.5 -291.5,-523.5 -291.5,-1133.5 1284,-1133.5 ; 2173,-1133.5 2173,-523.5 ; 3440,-726.83 3440,-523.5 ; 4280,-726.83 4280,-523.5 ; 4902,-1140 4902,-937.17
  text "COMPONENTS MARKED 'DNP' SHOULD  / NOT BE POPULATED." at 1150,-350 h60
  text "ASSEMBLY VARIANT:" at 1153,-434 h60
  text ".VariantName" at 2189,-434 h60
  text "PCB VIEWED FROM TOP SIDE" at -228.5,-655.67 h60
  text "BOARD #:" at 2248,-655.67 h60
  text ".PRJ_Number" at 2793.5,-655.67 h60
  text "REV:" at 3638,-655.67 h60
  text ".PCB_Rev" at 3929.5,-655.67 h60
  text "SVN REV:" at 4476,-655.67 h60
  text ".VersionControl_RevNumber" at 4982,-655.67 h60
  text "TID #:" at 2248,-859 h60
  text ".TID" at 2793.5,-859 h60
  text "PLOT NAME =" at -228.5,-1064.34 h60
  text ".plot_File_Name" at 577,-1064.34 h60
  text "GENERATED    :" at 2250,-1064.34 h60
  text ".Print_Date" at 3119.5,-1064.34 h60
  text ".Print_Time" at 3848.5,-1064.34 h60
  text "TEXAS INSTRUMENTS" at 5113,-1064.34 h60
M6 Assembly Bottom:
  lines w10: -292.5,-727.33 6309.5,-727.33 ; -290.5,-930.67 6309.5,-930.67 ; 1115.5,-1140.5 1115.5,-937.67 ; 1737.5,-727.33 1737.5,-524 ; 2577.5,-727.33 2577.5,-524 ; 3844.5,-1134 3844.5,-524 ; 4733.5,-1134 6309,-1134 6309,-524 -292.5,-524 -292.5,-1134 2304.5,-1134 6309.5,-1134 6309.5,-524
  text "COMPONENTS MARKED 'DNP' SHOULD NOT BE POPULATED." at 6102,-318 h60
  text ".VariantName" at 5058,-434 h60
  text "ASSEMBLY VARIANT:" at 6097,-434 h60
  text ".VersionControl_RevNumber" at 1035.5,-656.17 h60
  text "SVN REV:" at 1541.5,-656.17 h60
  text ".PCB_Rev" at 2088,-656.17 h60
  text "REV:" at 2379.5,-656.17 h60
  text ".PRJ_Number" at 3224,-656.17 h60
  text "BOARD #:" at 3769.5,-656.17 h60
  text "PCB VIEWED FROM BOTTOM SIDE" at 6246,-656.17 h60
  text ".TID" at 3224,-859.5 h60
  text "TID #:" at 3769.5,-859.5 h60
  text "TEXAS INSTRUMENTS" at 904.5,-1064.84 h60
  text ".Print_Time" at 2169,-1064.84 h60
  text ".Print_Date" at 2898,-1064.84 h60
  text "GENERATED    :" at 3767.5,-1064.84 h60
  text ".plot_File_Name" at 5440.5,-1064.84 h60
  text "PLOT NAME =" at 6246,-1064.84 h60
M9 Title Sheet:
  drawing of 57 lines, arcs and shapes, not listed
  text "1" at 739.84,8036.5 h70
  text "2" at 3235.5,8036.5 h70
  text "3" at 5724.84,8036.5 h70
  text "4" at 8231.51,8036.5 h70
  text "5" at 10730.5,8036.5 h70
  text "6" at 13235.5,8036.5 h70
  text "A" at -416.5,6893.5 h70
  text "A" at 14383.5,6893.5 h70
  text "5" at 7070.5,5617.13 h70
  text "B" at -416.5,4513.5 h70
  text "B" at 14383.5,4513.5 h70
  text "C" at -416.5,2138.5 h70
  text "C" at 14383.5,2138.5 h70
  text "PROJECT TITLE:" at 11343.5,277.5 h45
  text ".PRJ_Title" at 11393.5,144.17 h70
  text "DESIGNED FOR:" at 11343.5,-23.5 h45
  text ".PRJ_Customer" at 11393.5,-163.5 h70
  text "D" at -416.5,-231.5 h70
  text "D" at 14383.5,-231.5 h70
  text "FILE NAME:" at 11343.5,-323.5 h45
  text ".PCB_File_Name_No_Path" at 11393.5,-443.5 h70
  text "Texas Instruments (TI) and/or its licensors do not warrant the accuracy or completeness of this specification" at 6374,-605.34 h45
  text "ENGINEER:" at 11343.5,-613.5 h45
  text "LAYOUT BY:" at 12848.5,-613.5 h45
  text "or any information contained therein. TI and/or its licensors do not warrant that this design will meet" at 6329.01,-718 h45
  text ".PRJ_Engineer" at 11393.5,-768.49 h70
  text ".PCB_Layout" at 12899,-768.49 h70
  text "5" at 10630.5,-783.5 h70
  text "the specifications, will be suitable for your application or fit for any particular purpose, or will operate in" at 6329.01,-830.67 h45
  text ".Layer_Name" at 577,-858.49 h60
  text "ALTIUM DESIGNER VERSION:" at 12848.5,-923.5 h45
  text "an implementation. TI and/or its licensors do not warrant that the design is production worthy. You should" at 6329.01,-943.33 h45
  text "completely validate and test your design implementation to confirm the system functionality for your application." at 6374,-1056 h45
  text ".print_Scale" at 11393.5,-1056.83 h70
  text ".Application_BuildNumber" at 12899,-1056.83 h70
  text "1" at 739.84,-1263.5 h70
  text "2" at 3235.5,-1263.5 h70
  text "3" at 5724.84,-1263.5 h70
  text "4" at 8231.51,-1263.5 h70
  text "5" at 10730.5,-1263.5 h70
  text "6" at 13235.5,-1263.5 h70
M10 Fab Notes:
  drawing of 173 lines, arcs and shapes, not listed
  text "DESIGN INFORMATION" at 12378.02,6201 h60
  text "MIN. TRACK WIDTH:" at 11733.46,6021 h60
  text "8" at 12829.7,6021 h60
  text "MIL" at 12984.46,6021 h60
  text "6" at 12830,5890 h60
  text "MIN. CLEARANCE:" at 11733.46,5889 h60
  text "MIL" at 12984.46,5889 h60
  text "MIN. VIA PAD SIZE:" at 11733.46,5757 h60
  text "24" at 12799.71,5757 h60
  text "MIL" at 12984.46,5757 h60
  text "0.05mm (2MIL)" at 12428.46,5615.29 h60
  text "MINIMUM ANNULAR RING" at 11404.23,5611 h60
  text "EXTERNAL" at 13136.46,5611 h60
  text "PER" at 11604.23,5493 h60
  text "IPC-D-275 CLASS 2 LEVEL C" at 11824.23,5493 h60
  text "MIL, HOLES" at 13312.46,5380.71 h60
  text "+/-" at 12920,5380 h60
  text "+/-" at 13774,5380 h60
  text "REGISTRATION TOLERANCES:" at 11404.23,5375 h60
  text "METAL" at 12604,5375 h60
  text "5" at 13180.2,5375 h60
  text "3" at 14013.2,5375 h60
  text "MIL" at 14129.46,5375 h60
  text "+/-" at 13774,5262 h60
  text "HOLE SIZE TOLERANCE (UNLESS OTHERWISE SPECIFIED):" at 11404.23,5257 h60
  text "3" at 14013.2,5257 h60
  text "MIL" at 14129.46,5257 h60
  text "MATERIAL:" at 11329.46,5047.54 h60
  text "FR-4 High Tg" at 12315.9,4907.21 h60
  text "FR-408" at 11750.46,4898.64 h60
  text "OTHER" at 13238.46,4898.64 h60
  text "X" at 12161,4895 h60
  text "62 MIL (1.6mm) +/-10%" at 12070.56,4735.92 h60
  text "THICKNESS:" at 11404.23,4731.64 h60
  text "X" at 11942.4,4731.64 h60
  text "OTHER" at 13355.46,4731.64 h60
  text "TOLERANCE:" at 11404.23,4573.64 h60
  text "X" at 12243.53,4573.64 h60
  text "ANSI IPC-6012 TYPE 3 CLASS 2" at 12430.48,4573.64 h60
  text "OTHER +/-" at 12430.46,4417.64 h60
  text "BOW & TWIST:" at 11404.23,4260.64 h60
  text "X" at 12243.53,4260.64 h60
  text "ANSI IPC-6012 TYPE 3 CLASS 2" at 12430.48,4260.64 h60
  text "OTHER +/-" at 12430.46,4102.13 h60
  text "DRILLING:" at 11329.46,3963.64 h60
  text "REFERENCE:" at 11404.23,3846.64 h60
  text "X" at 12052.46,3846.64 h60
  text "AS SHOWN" at 12239.46,3846.64 h60
  text "X" at 12953.46,3846.64 h60
  text "NC_DRILL FILES" at 13090.46,3846.64 h60
  text "X" at 13270,3690 h60
  text "PTH COPPER THICKNESS:" at 11404.23,3688.64 h60
  text "20-30 um" at 12671.46,3688.64 h60
  text "OTHER" at 13388.46,3688.64 h60
  text "35 um" at 13711.46,3688.64 h60
  text "BOARD FINISH:" at 11329.46,3529.64 h60
  text "SILKSCREEN:" at 11484.68,3411.64 h60
  text "X" at 12433.46,3411.64 h60
  text "TOP" at 12559.46,3411.64 h60
  text "BOTTOM" at 13070.46,3411.64 h60
  text "SILKSCREEN COLOR:" at 11484.68,3244.64 h60
  text "X" at 12432.42,3244.64 h60
  text "WHITE" at 12559.46,3244.64 h60
  text "OTHER" at 13070.46,3244.64 h60
  text "X" at 12563.42,3085.44 h60
  text "GREEN" at 12690.46,3085.44 h60
  text "OTHER" at 13308.46,3085.44 h60
  text "SOLDER RESIST COLOR:" at 11484.68,3074.64 h60
  text "X" at 12563.42,2915.44 h60
  text "MATTE" at 12690.46,2915.44 h60
  text "SEMI-GLOSS" at 13308,2914.8 h60
  text "IMMERSION GOLD (ENIG)" at 12390.46,2726.92 h60
  text "ENEPIG" at 13728,2723.64 h60
  text "SURFACE FINISH:" at 11329.46,2722.64 h60
  text "X" at 12203.51,2722.64 h60
  text "IMM. TIN/SILVER OR EQUIV" at 11659,2565.64 h60
  text "OTHER" at 13090.46,2565.64 h60
  text "ARRAY/PANEL:" at 11329.46,2386.64 h60
  text "CUT AND TRIM PER M1 BOARD OUTLINE" at 12390.46,2382.35 h60
  text "N.C. ROUTE" at 12390.46,2230.64 h60
  text "V. SCORE" at 13256.46,2230.64 h60
  text "X" at 12200,2230 h60
  text "CERTIFICATION:" at 11329.46,2093.64 h60
  text "MATERIALS AND WORKMANSHIP FOR ALL PCBS" at 12054.46,2093.64 h60
  text "TO MEET OR EXCEED THE REQUIREMENTS OF:" at 12054.46,1995.64 h60
  text "X" at 11680.96,1859.13 h60
  text "ANSI IPC-A-600F CLASS ->" at 11819.96,1859.13 h60
  text "X" at 13459.02,1859.13 h60
  text "2" at 13577.96,1859.14 h60
  text "1" at 13262.96,1857.64 h60
  text "3" at 13931.96,1857.64 h60
  text "X" at 12495.02,1699.64 h60
  text "RoHS" at 12631.96,1699.64 h60
  text "OTHER" at 13276.36,1699.64 h60
  text "PER ORDER" at 13673.42,1699.64 h60
  text "ALL BOARDS MUST MEET OR EXCEED UL94-V0 REQUIREMENTS." at 11357,1534 h60
  text "PCB MUST BEAR THE UL94V-0 UL REGISTERED MATERIAL ID NUMBER" at 11357,1414 h60
  text "ADDITIONAL REQUIREMENTS:" at 11329.46,1240.64 h60
  text "MICROSECTION:" at 11404.23,1125.64 h60
  text "YES" at 12309.96,1125.64 h60
  text "REQUIRED" at 13171.46,969.49 h60
  text "BARE BOARD ELEC. TEST:" at 11404.23,966.64 h60
  text "NONE" at 12709.96,966.64 h60
  text "PER ORDER" at 13763.46,966.64 h60
  text "X" at 13630,960 h60
  text ".Layer_Name" at 577,-858.49 h60
M11 Gerber Information:
  lines w10: -292,-930.17 6308,-930.17 ; -292,-726.83 6310,-726.83 ; -292,-523.5 -292,-1133.5 3713,-1133.5 6310,-1133.5 6310,-523.5 -291.5,-523.5 -291.5,-1133.5 1284,-1133.5 ; 2173,-1133.5 2173,-523.5 ; 3440,-726.83 3440,-523.5 ; 4280,-726.83 4280,-523.5 ; 4902,-1140 4902,-937.17
  text "ALL ARTWORK VIEWED FROM TOP SIDE" at -228.5,-655.67 h60
  text "BOARD #:" at 2248,-655.67 h60
  text ".PRJ_Number" at 2793.5,-655.67 h60
  text "REV:" at 3638,-655.67 h60
  text ".PCB_Rev" at 3929.5,-655.67 h60
  text "SVN REV:" at 4476,-655.67 h60
  text ".VersionControl_RevNumber" at 4982,-655.67 h60
  text "LAYER NAME =" at -228.5,-858.49 h60
  text "TID #:" at 2248,-859 h60
  text ".TID" at 2793.5,-859 h60
  text "PLOT NAME =" at -228.5,-1064.34 h60
  text ".plot_File_Name" at 577,-1064.34 h60
  text "GENERATED    :" at 2250,-1064.34 h60
  text ".Print_Date" at 3119.5,-1064.34 h60
  text ".Print_Time" at 3848.5,-1064.34 h60
  text "TEXAS INSTRUMENTS" at 5113,-1064.34 h60
M12 Stackup:
  drawing of 295 lines, arcs and shapes, not listed
  text "Layer" at 9771.2,7830 h60
  text "Name" at 10181.11,7830 h60
  text "Material" at 11120.85,7830 h60
  text "Thickness" at 11980.62,7830 h60
  text "Constant" at 12630.46,7830 h60
  text "Board Layer Stack" at 13200.32,7830 h60
  text "1" at 9771.2,7710 h60
  text "Top Overlay" at 10181.11,7710 h60
  text "2" at 9771.2,7590 h60
  text "Top Solder" at 10181.11,7590 h60
  text "Solder Resist" at 11120.85,7590 h60
  text "0.40mil" at 11980.62,7590 h60
  text "3.5" at 12630.46,7590 h60
  text "Note: TOP & BOTTOM is 70um base  / copper + 25um plating  / during manufacturing" at 8180,7560 h47.24
  text "3" at 9771.2,7470 h60
  text "Top Layer" at 10181.11,7470 h60
  text "Copper" at 11120.85,7470 h60
  text "3.74mil" at 11980.62,7470 h60
  text "4" at 9771.2,7350 h60
  text "Dielectric1" at 10181.11,7350 h60
  text "2x 7628" at 11120.85,7350 h60
  text "13.78mil" at 11980.62,7350 h60
  text "4.2" at 12630.46,7350 h60
  text "5" at 9771.2,7230 h60
  text "Signal Layer 1" at 10181.11,7230 h60
  text "Copper" at 11120.85,7230 h60
  text "1.38mil" at 11980.62,7230 h60
  text "6" at 9771.2,7110 h60
  text "Dielectric 3" at 10181.11,7110 h60
  text "FR-4" at 11120.85,7110 h60
  text "27.95mil" at 11980.62,7110 h60
  text "4.2" at 12630.46,7110 h60
  text "7" at 9771.2,6990 h60
  text "Signal Layer 2" at 10181.11,6990 h60
  text "Copper" at 11120.85,6990 h60
  text "1.38mil" at 11980.62,6990 h60
  text "8" at 9771.2,6870 h60
  text "Dielectric 2" at 10181.11,6870 h60
  text "2x 7628" at 11120.85,6870 h60
  text "13.78mil" at 11980.62,6870 h60
  text "4.2" at 12630.46,6870 h60
  text "9" at 9771.2,6750 h60
  text "Bottom Layer" at 10181.11,6750 h60
  text "Copper" at 11120.85,6750 h60
  text "3.74mil" at 11980.62,6750 h60
  text "10" at 9771.2,6630 h60
  text "Bottom Solder" at 10181.11,6630 h60
  text "Solder Resist" at 11120.85,6630 h60
  text "0.40mil" at 11980.62,6630 h60
  text "3.5" at 12630.46,6630 h60
  text "11" at 9771.2,6510 h60
  text "Bottom Overlay" at 10181.11,6510 h60
  text ".Layer_Name" at 577,-858.49 h60
M13 Component Bodies Top:
  text ".Layer_Name" at 577,-858.49 h60
M14 Component Bodies Bottom:
  text ".Layer_Name" at 577,-858.49 h60
M15 Courtyards Top:
  text ".Layer_Name" at 577,-858.49 h60
M16 Courtyards Bottom:
  text ".Layer_Name" at 577,-858.49 h60
Drill Drawing:
  circle w10: c8037.72,692.52 r27.63
  lines w10: 8010.09,195.24 8037.72,167.62 8065.34,195.24 8037.72,222.87 8010.09,195.24 ; 8010.09,291.94 8065.34,291.94 8065.34,347.19 8010.09,347.19 8010.09,291.94 ; 8010.09,416.26 8037.72,430.07 8065.34,416.26 8051.53,443.88 8065.34,471.51 8037.72,457.7 8010.09,471.51 8023.9,443.88 8010.09,416.26 ; 8010.09,554.39 8023.9,554.39 8037.72,540.58 8051.53,554.39 8065.34,554.39 8051.53,568.2 8065.34,582.02 8051.53,582.02 8037.72,595.83 8023.9,582.02 8010.09,582.02 8023.9,568.2 8010.09,554.39 ; 8010.09,803.03 8023.9,803.03 8023.9,789.22 8051.53,789.22 8051.53,803.03 8065.34,803.03 8065.34,830.66 8051.53,830.66 8051.53,844.47 8023.9,844.47 8023.9,830.66 8010.09,830.66 8010.09,803.03 ; 8010.09,913.54 8010.09,927.35 8023.9,941.16 8010.09,954.98 8010.09,968.79 8023.9,968.79 8037.72,954.98 8051.53,968.79 8065.34,968.79 8065.34,954.98 8051.53,941.16 8065.34,927.35 8065.34,913.54 8051.53,913.54 8037.72,927.35 8023.9,913.54 8010.09,913.54
  lines w12: 7960,130.32 11191.49,130.32 ; 7960,1000.56 11191.49,1000.56 ; 8297.86,6 8297.86,1124.88 ; 8629.86,6 8629.86,1124.88 ; 9266.43,6 9266.43,1124.88 ; 9525.57,6 9525.57,1124.88 ; 9900.72,6 9900.72,1124.88 ; 10625.05,6 10625.05,1124.88 ; 7960,6 11191.49,6 11191.49,1124.88 7960,1124.88 7960,6
  text "Symbol" at 8034.59,1037.86 h72
  text "Quantity" at 8335.16,1037.86 h72
  text "Finished Hole Size" at 8667.16,1037.86 h72
  text "Plated" at 9303.72,1037.86 h72
  text "Hole Type" at 9562.86,1037.86 h72
  text "Drill Layer Pair" at 9938.02,1037.86 h72
  text "Hole Tolerance" at 10662.35,1037.86 h72
  text "23" at 8335.16,913.54 h60
  text "125.00mil (3.175mm)" at 8667.16,913.54 h60
  text "NPTH" at 9303.72,913.54 h60
  text "Round" at 9562.86,913.54 h60
  text "Top Layer - Bottom Layer" at 9938.02,913.54 h60
  text "61" at 8335.16,789.22 h60
  text "7.87mil (0.200mm)" at 8667.16,789.22 h60
  text "PTH" at 9303.72,789.22 h60
  text "Round" at 9562.86,789.22 h60
  text "Top Layer - Bottom Layer" at 9938.02,789.22 h60
  text "1730" at 8335.16,664.9 h60
  text "12.00mil (0.305mm)" at 8667.16,664.9 h60
  text "PTH" at 9303.72,664.9 h60
  text "Round" at 9562.86,664.9 h60
  text "Top Layer - Bottom Layer" at 9938.02,664.9 h60
  text "48" at 8335.16,540.58 h60
  text "39.37mil (1.000mm)" at 8667.16,540.58 h60
  text "PTH" at 9303.72,540.58 h60
  text "Round" at 9562.86,540.58 h60
  text "Top Layer - Bottom Layer" at 9938.02,540.58 h60
  text "2" at 8335.16,416.26 h60
  text "45.28mil (1.150mm)" at 8667.16,416.26 h60
  text "PTH" at 9303.72,416.26 h60
  text "Round" at 9562.86,416.26 h60
  text "Top Layer - Bottom Layer" at 9938.02,416.26 h60
  text "8" at 8335.16,291.94 h60
  text "90.55mil (2.300mm)" at 8667.16,291.94 h60
  text "PTH" at 9303.72,291.94 h60
  text "Round" at 9562.86,291.94 h60
  text "Top Layer - Bottom Layer" at 9938.02,291.94 h60
  text "4" at 8335.16,167.62 h60
  text "270.00mil (6.858mm)" at 8667.16,167.62 h60
  text "PTH" at 9303.72,167.62 h60
  text "Round" at 9562.86,167.62 h60
  text "Top Layer - Bottom Layer" at 9938.02,167.62 h60
  text "1876 Total" at 8335.16,43.3 h60
  text ".Layer_Name" at 577,-858.49 h60
M17 Embedded Cavity:
  text ".Layer_Name" at 577,-858.49 h60
M18 Embedded Assembly:
  text ".Layer_Name" at 577,-858.49 h60
M19 Embedded Keepout:
  text ".Layer_Name" at 577,-858.49 h60
Top Overlay - Custom:
  region: 7400,7000 7400,7300 7300,7300 7300,7000
  region: 7500,5300 7470,5330 7530,5330
  region: 7800,4620 7830,4590 7770,4590
  region: 7800,3720 7830,3690 7770,3690
  region: 7710,2380 7680,2410 7740,2410
  lines w10: 7460,3850 7460,3860 7470,3870 7500,3870 ; 7460,3940 7460,3930 7470,3920 7500,3920 ; 7570,1750 7650,1750 ; 7570,1950 7650,1950 ; 7570,2150 7650,2150 ; 7710,2580 7840,2580 ; 7710,2650 7840,2650 ; 7710,2720 7840,2720 ; 7710,2790 7840,2790 ; 7710,3590 7690,3590 7680,3580 7680,3540 7680,2890 7710,2860 ; 7710,2860 7840,2860 7840,2510 7710,2510 7710,2860 ; 7570,1550 7650,1550 7650,2350 7570,2350 7570,1550 ; 7760,1330 7840,1330 7840,1530 7760,1530 7760,1330
  text ".PRJ_Number" at 7270,6900 h60 r90
  text ".PCB_Rev" at 7380,6900 h60 r90
  text "PS4" at 2700,6800 h60
  text "EN4" at 7420,6490 h35 r90
  text "J701" at 7690,5470 h35
  text "EN3" at 7420,5400 h35 r90
  text "PS3" at 2700,5300 h60
  text "J800" at 6880,5290 h35
  text "CFG0" at 6750,4380 h35 r90
  text "CFG1" at 6820,4380 h35 r90
  text "ON" at 6900,4070 h35 r90
  text "ST1" at 7480,3960 h35 r90
  text "PS2" at 2700,3800 h60
  text "ST2" at 7480,3740 h35 r90
  text "J702" at 7690,3640 h35
  text "EN2" at 7420,3470 h35 r90
  text "BCK" at 7730,2810 h35
  text "BST" at 7730,2740 h35
  text "FLT" at 7730,2670 h35
  text "RST" at 7730,2600 h35
  text "SDN" at 7730,2530 h35
  text "J700" at 7690,2430 h35
  text "EN1" at 7420,2380 h35 r90
  text "PS1" at 2700,2300 h60
  text "P48V" at 7630,2180 h35 r90
  text "P12V" at 7630,1990 h35 r90
  text "P10V" at 7630,1790 h35 r90
  text "P3V3" at 7630,1590 h35 r90
  text "8xGND" at 7820,1350 h35 r90
  text "KL41" at 3500,60 h60
  text "KL31" at 5050,60 h60

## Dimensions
0,0 to 2930,0 on M2 Board Dimensions
0,0 to 6100,-470 on M2 Board Dimensions
0,-400 to 1000,-400 on M2 Board Dimensions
